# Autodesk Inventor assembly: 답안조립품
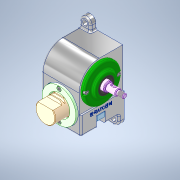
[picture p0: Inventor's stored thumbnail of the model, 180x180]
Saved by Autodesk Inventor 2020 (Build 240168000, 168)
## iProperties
Created: 2023-09
Part Number: 답안조립품
Document SubType Name: Assembly
Designer: oem
Author: oem
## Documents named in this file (11)
- C:\Users\oem\Desktop\730906V1005\답안조립품.iam
- C:\Users\oem\Desktop\730906V1005\본체.ipt
- C:\Users\oem\Desktop\730906V1005\부시 커버.ipt
- C:\Users\oem\Desktop\730906V1005\가이드 부시.ipt
- C:\Users\oem\Desktop\730906V1005\래크.ipt
- C:\Users\oem\Desktop\730906V1005\앞커버.ipt
- C:\Users\oem\Desktop\730906V1005\오일 실 17 30 5.ipt
- C:\Users\oem\Desktop\730906V1005\베어링 6003.ipt
- C:\Users\oem\Desktop\730906V1005\피니언.ipt
- C:\Users\oem\Desktop\730906V1005\스톱퍼.ipt
- C:\Users\oem\Desktop\730906V1005\볼트 M4.ipt
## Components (3 placed, 2 different names)
1. 가이드 부시:1
2. 가이드 부시:2
3. 피니언:1
